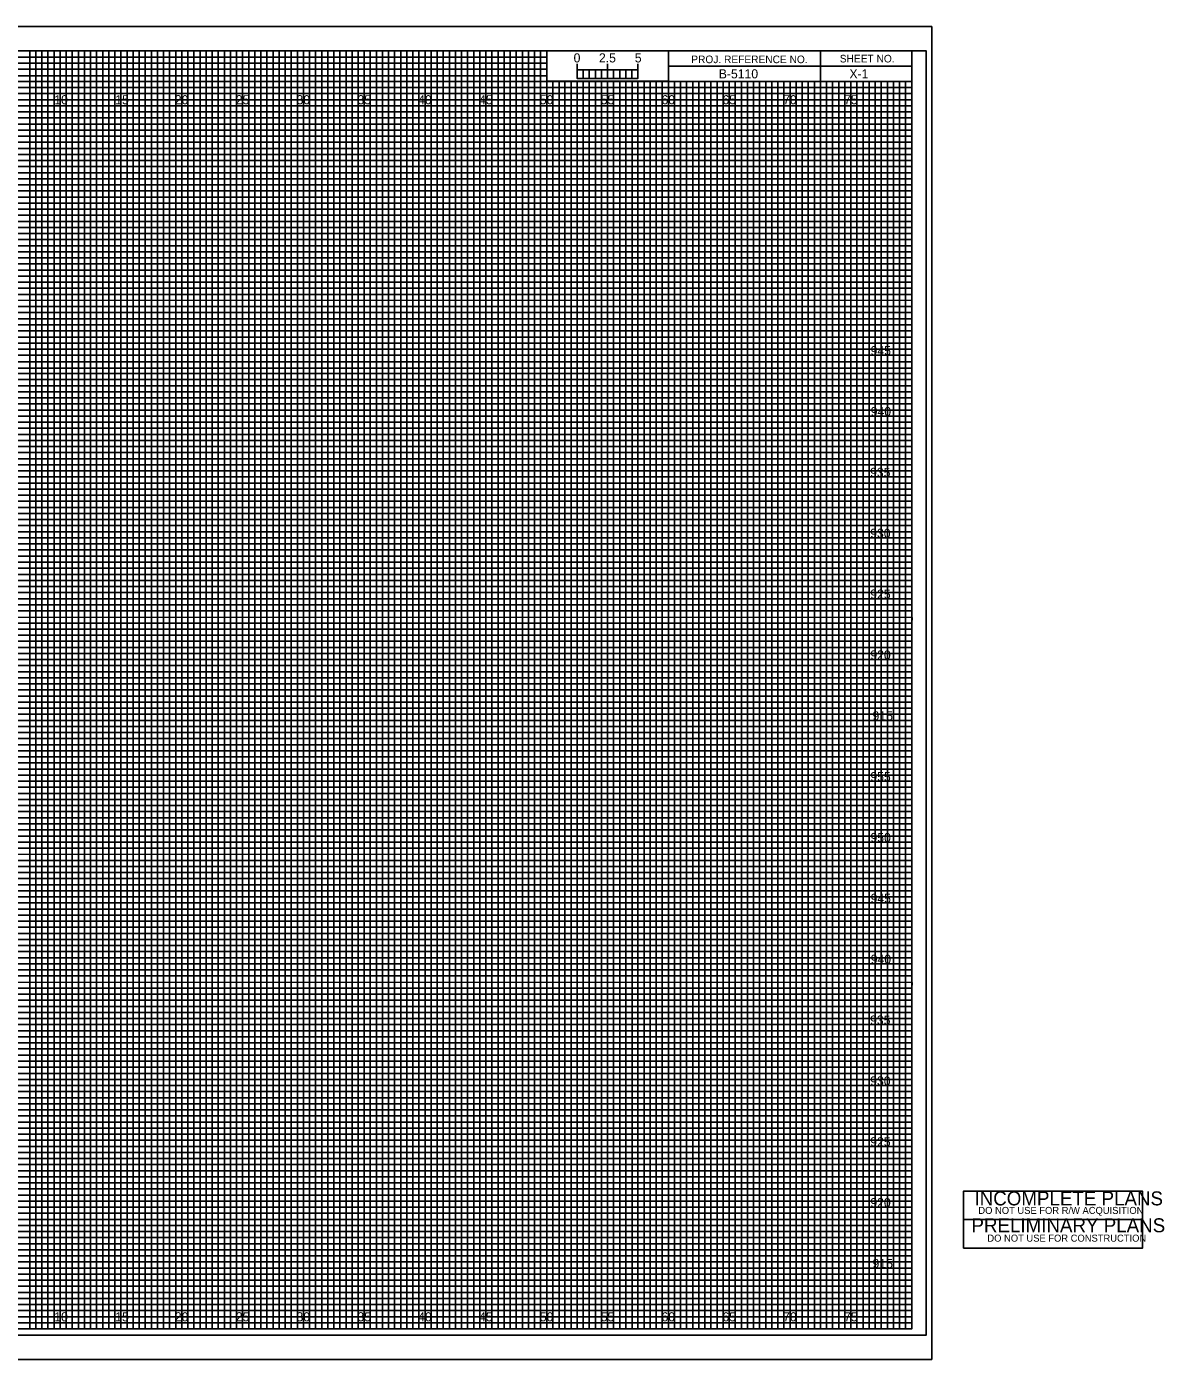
# Model space of a CAD drawing. Extents: x -7 to 181, y -2 to 107.
# Drawn here: x 87.2 to 180.8, y -2.5 to 107 of the extents above; entities that cross this region are included whole.
import ezdxf

# ---------------------------------------------------------------- set-up
doc = ezdxf.new("R2010")
doc.units = 0
for name, color, linetype in [('Prop XS Bar Scale Labels', 7, 'Continuous'), ('Prop XS Elevation Labels', 7, 'Continuous'), ('Prop XS Offset Labels', 7, 'Continuous'), ('Prop XS Project Number', 7, 'Continuous'), ('Prop XS Sheet Number', 7, 'Continuous'), ('Sheet Cross Section CELL', 7, 'Continuous'), ('Sheet Cross Section Grid Major CELL', 7, 'Continuous'), ('Sheet Cross Section Grid Middle CELL', 7, 'Continuous'), ('Sheet Cross Section Grid Minor 1 CELL', 7, 'Continuous'), ('Sheet Cross Section Grid Minor 2 CELL', 7, 'Continuous'), ('Sheet Cross Section Scale CELL', 7, 'Continuous'), ('Sheet Cutting Line CELL', 7, 'Continuous'), ('Sheet DOT Grid CELL', 7, 'Continuous'), ('Sheet Plot Border Inside CELL', 7, 'Continuous'), ('Sheet Plot Border Outside CELL', 7, 'Continuous'), ('Sheet Sticker Incomplete CELL', 7, 'Continuous'), ('Sheet Sticker Preliminary CELL', 7, 'Continuous')]:
    doc.layers.add(name, color=color, linetype=linetype)

msp = doc.modelspace()

# ---------------------------------------------------------------- linework, layer by layer
at = {"layer": 'Sheet Cross Section CELL'}
for p, q in [((152.5, 105), (152.5, 102.5)), ((152.5, 102.5), (152.5, 105)), ((160, 103.75), (140, 103.75)), ((140, 103.75), (140, 102.5)), ((140, 102.5), (160, 102.5))]:
    msp.add_line(p, q, dxfattribs=at)
for points in [[(160, 105), (0, 105), (0, 0), (160, 0)], [(140, 105), (130, 105), (130, 102.52), (140, 102.52)], [(160, 105), (140, 105), (140, 102.5), (160, 102.5)]]:
    msp.add_lwpolyline(points, close=True, dxfattribs=at)
at = {"layer": 'Sheet Cross Section Grid Major CELL'}
for p, q in [((95, 105), (90, 105)), ((90, 105), (90, 0)), ((95, 0), (95, 105)), ((105, 105), (100, 105)), ((100, 105), (100, 0)), ((105, 0), (105, 105)), ((115, 105), (110, 105)), ((110, 105), (110, 0)), ((115, 0), (115, 105)), ((125, 105), (120, 105)), ((120, 105), (120, 0)), ((125, 0), (125, 105)), ((130, 105), (130, 0)), ((135, 0), (135, 102.5)), ((145, 102.5), (140, 102.5)), ((140, 102.5), (140, 0)), ((145, 0), (145, 102.5)), ((155, 102.5), (150, 102.5)), ((150, 102.5), (150, 0)), ((155, 0), (155, 102.5)), ((90, 0), (85, 0)), ((100, 0), (95, 0)), ((110, 0), (105, 0)), ((120, 0), (115, 0)), ((130, 0), (125, 0)), ((140, 0), (135, 0)), ((150, 0), (145, 0)), ((160, 0), (155, 0)), ((160, 0), (160, 0))]:
    msp.add_line(p, q, dxfattribs=at)
for points in [[(0, 100), (160, 100), (160, 95), (0, 95)], [(0, 90), (160, 90), (160, 85), (0, 85)], [(0, 80), (160, 80), (160, 75), (0, 75)], [(0, 70), (160, 70), (160, 65), (0, 65)], [(0, 60), (160, 60), (160, 55), (0, 55)], [(0, 50), (160, 50), (160, 45), (0, 45)], [(0, 40), (160, 40), (160, 35), (0, 35)], [(0, 30), (160, 30), (160, 25), (0, 25)], [(0, 20), (160, 20), (160, 15), (0, 15)], [(0, 10), (160, 10), (160, 5), (0, 5)]]:
    msp.add_lwpolyline(points, dxfattribs=at)
at = {"layer": 'Sheet Cross Section Grid Middle CELL'}
for points in [[(82.5, 0), (87.5, 0), (87.5, 105), (92.5, 105), (92.5, 0), (97.5, 0), (97.5, 105), (102.5, 105), (102.5, 0), (107.5, 0), (107.5, 105), (112.5, 105), (112.5, 0), (117.5, 0), (117.5, 105), (122.5, 105), (122.5, 0), (127.5, 0), (127.5, 105), (129.97, 105), (130, 105), (130, 102.5), (132.5, 102.5), (132.5, 0), (137.5, 0), (137.5, 102.5), (142.5, 102.5), (142.5, 0), (147.5, 0), (147.5, 102.5), (152.5, 102.5), (152.5, 0), (157.5, 0), (157.5, 102.5)], [(0, 102.5), (137.5, 102.5)], [(0, 92.5), (160, 92.5), (160, 97.5), (0, 97.5)], [(0, 82.5), (160, 82.5), (160, 87.5), (0, 87.5)], [(0, 72.5), (160, 72.5), (160, 77.5), (0, 77.5)], [(0, 62.5), (160, 62.5), (160, 67.5), (0, 67.5)], [(0, 52.5), (160, 52.5), (160, 57.5), (0, 57.5)], [(0, 42.5), (160, 42.5), (160, 47.5), (0, 47.5)], [(0, 32.5), (160, 32.5), (160, 37.5), (0, 37.5)], [(0, 22.5), (160, 22.5), (160, 27.5), (0, 27.5)], [(0, 12.5), (160, 12.5), (160, 17.5), (0, 17.5)], [(0, 2.5), (160, 2.5), (160, 7.5), (0, 7.5)]]:
    msp.add_lwpolyline(points, dxfattribs=at)
at = {"layer": 'Sheet Cross Section Grid Minor 1 CELL'}
for p, q in [((0, 104.5), (130, 104.5)), ((130, 104.5), (130, 103.99)), ((130, 103.99), (0, 103.99)), ((0, 103.5), (130, 103.5)), ((130, 102.95), (0, 102.95)), ((130, 103.5), (130, 102.95)), ((0, 102), (160, 102))]:
    msp.add_line(p, q, dxfattribs=at)
for points in [[(0, 101.5), (135, 101.5), (160, 101.5), (160, 101), (0, 101)], [(0, 100.5), (160, 100.5), (160, 99.5), (0, 99.5)], [(0, 99), (160, 99), (160, 98.5), (0, 98.49)], [(0, 98), (160, 98), (160, 97), (0, 97)], [(0, 96.5), (160, 96.5), (160, 96), (0, 96)], [(0, 95.5), (160, 95.5), (160, 94.5), (0, 94.5)], [(0, 94), (160, 94), (160, 93.5), (0, 93.5)], [(0, 93), (160, 93), (160, 92), (0, 92)], [(0, 91.5), (160, 91.5), (160, 91), (0, 91)], [(0, 90.5), (160, 90.5), (160, 89.5), (0, 89.5)], [(0, 89), (160, 89), (160, 88.5), (0, 88.5)], [(0, 88), (160, 88), (160, 86.98), (160, 86.5), (160, 86), (0, 86)], [(0, 87), (160, 87), (160, 86.5), (0, 86.5)], [(0, 85.5), (160, 85.5), (160, 84.5), (0, 84.52)], [(0, 84.52), (160, 84.5), (160, 84), (0, 84)], [(0, 83.5), (160, 83.5), (160, 83), (0, 83)], [(0, 82), (160, 82), (160, 81.5), (0, 81.5)], [(0, 81), (160, 81), (160, 80.5), (0, 80.5)], [(-0.04, 79.45), (160, 79.45), (160, 78.94), (-0.04, 78.94)], [(0, 78.5), (160, 78.5), (160, 78), (0, 78)], [(0, 77), (160, 77), (160, 76.5), (0, 76.5)], [(0, 76), (160, 76), (160, 75.5), (0, 75.5)], [(0, 74.5), (160, 74.5), (160, 74), (0, 74)], [(0, 73.5), (160, 73.5), (160, 73), (0, 73)], [(0, 72), (160, 72), (160, 71.5), (0, 71.5)], [(0, 71), (160, 71), (160, 70.5), (0, 70.5)], [(0, 69.5), (160, 69.5), (160, 68.99), (0, 69)], [(0, 68.5), (160, 68.5), (160, 68), (0, 68)], [(0, 67), (160, 67), (160, 66.5), (0, 66.5)], [(0, 66), (160, 66), (160, 65.5), (0, 65.5)], [(0, 64.5), (160, 64.5), (160, 64), (0, 64)], [(0, 63.5), (160, 63.5), (160, 63), (0, 63)], [(0, 62), (160, 62), (160, 61.5), (0, 61.5)], [(0, 61), (160, 61), (160, 60.5), (0, 60.5)], [(0, 59.5), (160, 59.5), (160, 59), (0, 59)], [(0, 58.5), (160.03, 58.45), (160, 58), (0, 58)], [(0, 57), (160, 57), (160, 56.5), (0, 56.5)], [(0, 56), (160, 56), (160, 55.5), (0, 55.5)], [(0, 54.5), (160, 54.5), (160, 54), (0, 54)], [(0, 53.5), (160, 53.5), (160, 53), (0, 53)], [(0, 52), (160, 52), (160, 51.5), (0, 51.5)], [(0, 51), (160, 51), (160, 50.5), (0, 50.5)], [(0, 49.5), (160, 49.5), (160, 49), (0, 49)], [(0, 48.5), (160, 48.5), (160, 48), (0, 48)], [(0, 47), (160, 47), (160, 46.5), (0, 46.5)], [(0, 46), (160, 46), (160, 45.5), (0, 45.5)], [(0, 44.5), (160, 44.5), (160, 44), (0, 44)], [(0, 43.5), (160, 43.5), (160, 43), (0, 43)], [(0, 42), (160, 42), (160, 41.5), (0, 41.5)], [(0, 41), (160, 41), (160, 40.5), (0, 40.5)], [(0, 39.5), (160, 39.5), (160, 38.99), (0, 39)], [(0, 38.5), (160, 38.5), (160, 38), (0, 38)], [(0, 37), (160, 37), (160, 36.5), (0, 36.5)], [(0, 36), (160, 36), (160, 35.5), (0, 35.5)], [(0, 34.5), (160, 34.5), (160, 34), (0, 34)], [(0, 33.5), (160, 33.5), (160, 33), (0, 33)], [(0, 32), (160, 32), (160, 31.5), (0, 31.5)], [(0, 31), (160, 31), (160, 30.5), (0, 30.5)], [(0, 29.5), (160, 29.5), (160, 29), (0, 29)], [(0, 28.5), (160.03, 28.46), (160, 28), (0, 28)], [(0, 27), (160, 27), (160, 26.5), (0, 26.5)], [(0, 26), (160, 26), (160, 25.5), (0, 25.5)], [(0, 24.5), (160, 24.5), (160, 24), (0, 24)], [(0, 23.5), (160, 23.5), (160, 23), (0, 23)], [(0, 22), (160, 22), (160, 21.5), (0, 21.5)], [(0, 21), (160, 21), (160, 20.5), (0, 20.5)], [(0, 19.5), (160, 19.5), (160, 19), (0, 19)], [(0, 18.5), (160, 18.5), (160, 18), (0, 18)], [(0, 17), (160, 17), (160, 16.5), (0, 16.5)], [(0, 16), (160, 16), (160, 15.5), (0, 15.5)], [(0, 14.5), (160, 14.5), (160, 14), (0, 14)], [(0, 13.5), (160, 13.5), (160, 13), (0, 13)], [(0, 12), (160, 12), (160, 11.5), (0, 11.5)], [(0, 11), (160, 11), (160, 10.5), (0, 10.5)], [(0, 9.5), (160, 9.5), (160, 9), (0, 9)], [(0, 8.5), (160, 8.5), (160, 8), (0, 8)], [(0, 7), (160, 7), (160, 6.5), (0, 6.5)], [(0, 6), (160, 6), (160, 5.5), (0, 5.5)], [(0, 4.5), (160, 4.5), (160, 4), (0, 4)], [(0, 3.5), (160, 3.5), (160, 3), (0, 3)], [(0, 2), (160, 2), (160, 1.5), (0, 1.5)], [(0, 1), (160, 1), (160, 0.5), (0, 0.5)]]:
    msp.add_lwpolyline(points, dxfattribs=at)
at = {"layer": 'Sheet Cross Section Grid Minor 2 CELL'}
for p, q in [((133.5, 102.5), (133, 102.5)), ((133, 102.5), (133, 0)), ((133.5, 0), (133.5, 102.5)), ((134.5, 102.5), (134, 102.5)), ((134, 102.5), (134, 0)), ((134.5, 0), (134.5, 102.5)), ((133, 0), (132.5, 0)), ((134, 0), (133.5, 0))]:
    msp.add_line(p, q, dxfattribs=at)
for points in [[(87.5, 0), (88, 0), (88, 105), (88.5, 105), (88.5, 0)], [(88.5, 0), (89, 0), (89, 105), (89.5, 105), (89.5, 0)], [(90, 0), (90.5, 0), (90.5, 105), (91, 105), (91, 0)], [(91, 0), (91.5, 0), (91.5, 105), (92, 105), (92, 0)], [(92.5, 0), (93, 0), (93, 105), (93.5, 105), (93.5, 0)], [(93.5, 0), (94, 0), (94, 105), (94.5, 105), (94.5, 0)], [(95, 0), (95.5, 0), (95.5, 105), (96, 105), (96, 0)], [(96, 0), (96.5, 0), (96.5, 105), (97, 105), (97, 0)], [(97.5, 0), (98, 0), (98, 105), (98.5, 105), (98.5, 0)], [(98.5, 0), (99, 0), (99, 105), (99.5, 105), (99.5, 0)], [(100, 0), (100.5, 0), (100.5, 105), (101, 105), (101, 0)], [(101, 0), (101.5, 0), (101.5, 105), (102, 105), (102, 0)], [(102.5, 0), (103, 0), (103, 105), (103.5, 105), (103.5, 0)], [(103.5, 0), (104, 0), (104, 105), (104.5, 105), (104.5, 0)], [(105, 0), (105.5, 0), (105.5, 105), (106, 105), (106, 0)], [(106, 0), (106.5, 0), (106.5, 105), (107, 105), (107, 0)], [(107.5, 0), (108, 0), (108, 105), (108.5, 105), (108.5, 0)], [(108.5, 0), (109, 0), (109, 105), (109.5, 105), (109.5, 0)], [(110, 0), (110.5, 0), (110.5, 105), (111, 105), (111, 0)], [(111, 0), (111.5, 0), (111.5, 105), (112, 105), (112, 0)], [(112.5, 0), (113, 0), (113, 105), (113.5, 105), (113.5, 0)], [(113.5, 0), (114, 0), (114, 105), (114.5, 105), (114.5, 0)], [(115, 0), (115.5, 0), (115.5, 105), (116, 105), (116, 0)], [(116, 0), (116.5, 0), (116.5, 105), (117, 105), (117, 0)], [(117.5, 0), (118, 0), (118, 105), (118.5, 105), (118.5, 0)], [(118.5, 0), (119, 0), (119, 105), (119.5, 105), (119.5, 0)], [(120, 0), (120.5, 0), (120.5, 105), (121, 105), (121, 0)], [(121, 0), (121.5, 0), (121.5, 105), (122, 105), (122, 0)], [(122.5, 0), (123, 0), (123, 105), (123.5, 105), (123.5, 0)], [(123.5, 0), (124, 0), (124, 105), (124.5, 105), (124.5, 0)], [(125, 0), (125.5, 0), (125.5, 105), (126, 105), (126, 0)], [(126, 0), (126.5, 0), (126.5, 105), (127, 105), (127, 0)], [(127.5, 0), (128, 0), (128, 105), (128.5, 105), (128.5, 0)], [(128.5, 0), (129, 0), (129, 105), (129.5, 105), (129.5, 0)], [(130, 0), (130.5, 0), (130.5, 102.5), (131.01, 102.5), (131.01, 0)], [(131, 0), (131.5, 0), (131.5, 102.5), (132, 102.5), (132, 0)], [(135, 0), (135.49, 0), (135.49, 102.5), (136, 102.5), (136, 0)], [(136, 0), (136.5, 0), (136.5, 102.5), (137.03, 102.5), (137.03, 0)], [(137.5, 0), (138, 0), (138, 102.5), (138.5, 102.5), (138.5, 0)], [(138.5, 0), (139, 0), (139, 102.5), (139.5, 102.5), (139.5, 0)], [(140, 0), (140.5, 0), (140.5, 102.5), (141, 102.5), (141, 0)], [(141, 0), (141.5, 0), (141.5, 102.5), (142, 102.5), (142, 0)], [(142.5, 0), (143, 0), (143, 102.5), (143.5, 102.5), (143.5, 0)], [(143.5, 0), (144, 0), (144, 102.5), (144.5, 102.5), (144.5, 0)], [(145, 0), (145.5, 0), (145.5, 102.5), (146, 102.5), (146, 0)], [(146, 0), (146.5, 0), (146.5, 102.5), (147, 102.5), (147, 0)], [(147.5, 0), (148, 0), (148, 102.5), (148.5, 102.5), (148.5, 0)], [(148.5, 0), (149, 0), (149, 102.5), (149.5, 102.5), (149.5, 0)], [(150, 0), (150.5, 0), (150.5, 102.5), (151, 102.5), (151, 0)], [(151, 0), (151.5, 0), (151.5, 102.5), (152, 102.5), (152, 0)], [(152.5, 0), (153, 0), (153, 102.5), (153.5, 102.5), (153.5, 0)], [(153.5, 0), (154, 0), (154, 102.5), (154.5, 102.5), (154.5, 0)], [(155, 0), (155.5, 0), (155.5, 102.5), (156, 102.5), (156, 0)], [(156, 0), (156.5, 0), (156.5, 102.5), (157, 102.5), (157, 0)], [(157.5, 0), (158, 0), (158, 102.5), (158.5, 102.5), (158.5, 0)], [(158.5, 0), (159, 0), (159, 102.5), (159.5, 102.5), (159.5, 0)]]:
    msp.add_lwpolyline(points, dxfattribs=at)
at = {"layer": 'Sheet Cross Section Scale CELL'}
for p, q in [((132.5, 102.75), (132.5, 103.95)), ((132.5, 103.45), (132.5, 103.95)), ((135, 102.75), (135, 103.95)), ((137.5, 102.75), (137.5, 103.95)), ((137.5, 103.45), (137.5, 103.95))]:
    msp.add_line(p, q, dxfattribs=at)
for points in [[(137.5, 103.45), (132.5, 103.45), (132.5, 102.75), (137.5, 102.75)], [(132.5, 103.45), (133, 103.45), (133, 102.75), (132.5, 102.75)], [(133.5, 103.45), (134, 103.45), (134, 102.75), (133.5, 102.75)], [(134.5, 103.45), (135, 103.45), (135, 102.75), (134.5, 102.75)], [(135.5, 103.45), (136, 103.45), (136, 102.75), (135.5, 102.75)], [(136.5, 103.45), (137, 103.45), (137, 102.75), (136.5, 102.75)]]:
    msp.add_lwpolyline(points, close=True, dxfattribs=at)
at = {"layer": 'Sheet Cutting Line CELL'}
for p, q in [((161.65, 107), (-6.7, 107)), ((-6.7, -2.5), (161.65, -2.5))]:
    msp.add_line(p, q, dxfattribs=at)
at = {"layer": 'Sheet DOT Grid CELL'}
for p, q in [((90, 0), (90, 105)), ((95, 0), (95, 105)), ((100, 0), (100, 105)), ((105, 0), (105, 105)), ((110, 0), (110, 105)), ((115, 0), (115, 105)), ((120, 0), (120, 105)), ((125, 0), (125, 105)), ((130, 0), (130, 102.34)), ((135, 0), (135, 102.34)), ((140, 0), (140, 102.34)), ((145, 0), (145, 102.34)), ((150, 0), (150, 102.34)), ((155, 0), (155, 102.34)), ((0, 100), (160, 100)), ((0, 95), (160, 95)), ((0, 90), (160, 90)), ((0, 85), (160, 85)), ((0, 80), (160, 80)), ((0, 75), (160, 75)), ((0, 70), (160, 70)), ((0, 65), (160, 65)), ((0, 60), (160, 60)), ((0, 55), (160, 55)), ((0, 50), (160, 50)), ((0, 45), (160, 45)), ((0, 40), (160, 40)), ((0, 35), (160, 35)), ((0, 30), (160, 30)), ((0, 25), (160, 25)), ((0, 20), (160, 20)), ((0, 15), (160, 15)), ((0, 10), (160, 10)), ((0, 5), (160, 5))]:
    msp.add_line(p, q, dxfattribs=at)
at = {"layer": 'Sheet Plot Border Inside CELL'}
msp.add_lwpolyline([(-5.4, -0.5), (161.2, -0.5), (161.2, 105), (-5.4, 105)], close=True, dxfattribs=at)
at = {"layer": 'Sheet Plot Border Outside CELL'}
msp.add_lwpolyline([(-6.7, -2.5), (161.65, -2.5), (161.65, 107), (-6.7, 107)], close=True, dxfattribs=at)
at = {"layer": 'Sheet Sticker Incomplete CELL'}
msp.add_lwpolyline([(164.26, 8.98), (164.26, 11.33), (178.96, 11.33), (178.96, 8.98)], close=True, dxfattribs=at)
at = {"layer": 'Sheet Sticker Preliminary CELL'}
msp.add_lwpolyline([(164.26, 6.63), (164.26, 8.98), (178.96, 8.98), (178.96, 6.63)], close=True, dxfattribs=at)

# ---------------------------------------------------------------- texts
at = {"layer": 'Prop XS Bar Scale Labels'}
for s, p in [('2.5', (134.29, 104.06)), ('5', (137.24, 104.06))]:
    msp.add_text(s, height=0.75, dxfattribs=at).set_placement(p)
at = {"layer": 'Prop XS Elevation Labels'}
for s, p in [('945', (156.62, 80)), ('940', (156.63, 75)), ('935', (156.58, 70)), ('930', (156.59, 65)), ('925', (156.59, 60)), ('920', (156.6, 55)), ('915', (156.78, 50)), ('955', (156.6, 45)), ('950', (156.61, 40)), ('945', (156.62, 35)), ('940', (156.63, 30)), ('935', (156.58, 25)), ('930', (156.59, 20)), ('925', (156.59, 15)), ('920', (156.6, 10)), ('915', (156.78, 5))]:
    msp.add_text(s, height=0.75, dxfattribs=at).set_placement(p)
at = {"layer": 'Prop XS Offset Labels'}
for s, p in [('10', (89.52, 100.62)), ('15', (94.53, 100.62)), ('20', (99.43, 100.62)), ('25', (104.44, 100.62)), ('30', (109.43, 100.62)), ('35', (114.44, 100.62)), ('40', (119.43, 100.62)), ('45', (124.44, 100.62)), ('50', (129.43, 100.62)), ('55', (134.44, 100.62)), ('60', (139.43, 100.62)), ('65', (144.44, 100.62)), ('70', (149.43, 100.62)), ('75', (154.44, 100.62)), ('10', (89.52, 0.62)), ('15', (94.53, 0.62)), ('20', (99.43, 0.62)), ('25', (104.44, 0.62)), ('30', (109.43, 0.62)), ('35', (114.44, 0.62)), ('40', (119.43, 0.62)), ('45', (124.44, 0.62)), ('50', (129.43, 0.62)), ('55', (134.44, 0.62)), ('60', (139.43, 0.62)), ('65', (144.44, 0.62)), ('70', (149.43, 0.62)), ('75', (154.44, 0.62))]:
    msp.add_text(s, height=0.75, dxfattribs=at).set_placement(p)
at = {"layer": 'Prop XS Project Number'}
msp.add_text('B-5110', height=0.75, dxfattribs=at).set_placement((144.14, 102.75))
at = {"layer": 'Prop XS Sheet Number'}
msp.add_text('X-1', height=0.75, dxfattribs=at).set_placement((154.88, 102.75))
at = {"layer": 'Sheet Cross Section CELL'}
for s, p in [('PROJ. REFERENCE NO.', (141.88, 104)), ('SHEET NO.', (154.09, 104.06))]:
    msp.add_text(s, height=0.625, dxfattribs=at).set_placement(p)
at = {"layer": 'Sheet Cross Section Scale CELL'}
msp.add_text('0', height=0.75, dxfattribs=at).set_placement((132.21, 104.06))
at = {"layer": 'Sheet Sticker Incomplete CELL'}
for s, height, p in [('INCOMPLETE PLANS', 1.152, (165.16, 10.15)), ('DO NOT USE FOR R/W ACQUISITION', 0.576, (165.48, 9.45))]:
    msp.add_text(s, height=height, dxfattribs=at).set_placement(p)
at = {"layer": 'Sheet Sticker Preliminary CELL'}
for s, height, p in [('PRELIMINARY PLANS', 1.152, (164.91, 7.94)), ('DO NOT USE FOR CONSTRUCTION', 0.576, (166.22, 7.17))]:
    msp.add_text(s, height=height, dxfattribs=at).set_placement(p)

doc.saveas('drawing.dxf')
